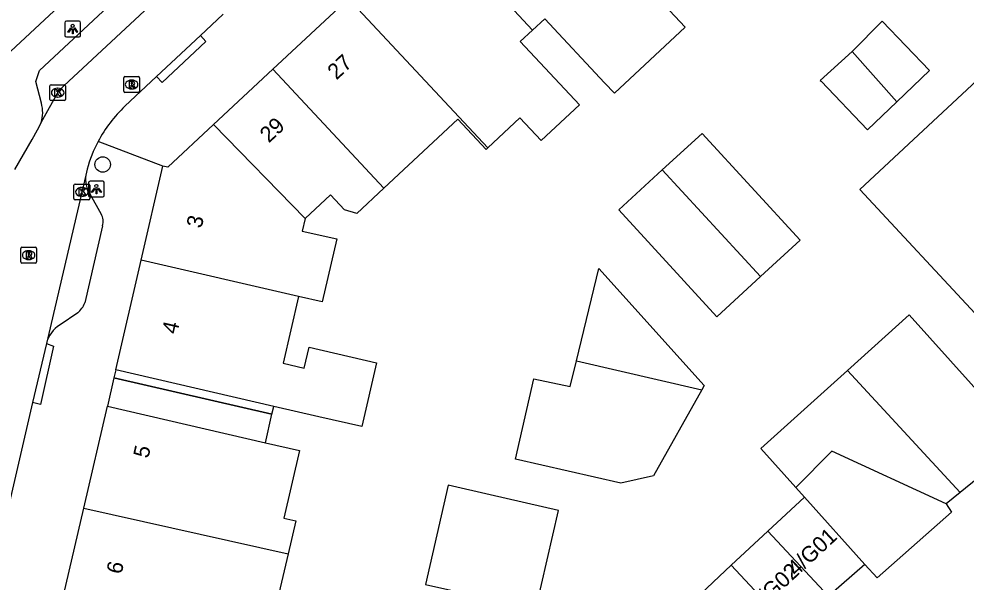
# Model space of a CAD drawing. Extents: x 161801 to 162379, y 382315 to 382832.
# Drawn here: x 161897.6 to 161957.7, y 382637.3 to 382673 of the extents above; entities that cross this region are included whole.
import ezdxf

# ---------------------------------------------------------------- set-up
doc = ezdxf.new("R2010")
doc.units = 0
for name, color, linetype in [('IMGEO_Boom', 7, 'Continuous'), ('IMGEO_Kolk', 7, 'Continuous'), ('IMGEO_Lichtpunt', 7, 'Continuous'), ('IMGEO_Pand', 7, 'Continuous'), ('IMGEO_Pand_nummerreeks', 7, 'Continuous'), ('IMGEO_Pand_overbouw', 7, 'Continuous'), ('IMGEO_Rijbaan_lokaal_open', 7, 'Continuous'), ('IMGEO_Rioolput', 7, 'Continuous'), ('IMGEO_Voetpad_open', 7, 'Continuous')]:
    doc.layers.add(name, color=color, linetype=linetype)

msp = doc.modelspace()

# ---------------------------------------------------------------- linework, layer by layer
at = {"layer": 'IMGEO_Boom'}
msp.add_circle((161902.962, 382663.801), 0.489, dxfattribs=at)
at = {"layer": 'IMGEO_Kolk'}
for p, q in [((161899.61, 382667.935), (161899.61, 382668.787)), ((161899.685, 382668.861), (161900.537, 382668.861)), ((161900.611, 382668.787), (161900.611, 382667.935)), ((161900.098, 382668.641), (161900.123, 382668.641)), ((161900.537, 382667.861), (161899.685, 382667.861)), ((161900.121, 382668.081), (161900.096, 382668.081)), ((161901.139, 382661.639), (161901.139, 382662.491)), ((161901.214, 382662.565), (161902.066, 382662.565)), ((161901.627, 382662.345), (161901.652, 382662.345)), ((161902.14, 382662.491), (161902.14, 382661.639)), ((161902.066, 382661.565), (161901.214, 382661.565)), ((161901.65, 382661.785), (161901.625, 382661.785))]:
    msp.add_line(p, q, dxfattribs=at)
for points in [[(161899.61, 382667.935), (161899.61, 382668.787)], [(161899.685, 382668.861), (161900.537, 382668.861)], [(161900.611, 382668.787), (161900.611, 382667.935)], [(161899.931, 382668.561), (161900.054, 382668.561), (161900.054, 382668.41), (161900.184, 382668.561), (161900.348, 382668.561), (161900.202, 382668.41), (161900.355, 382668.161), (161900.203, 382668.161), (161900.118, 382668.325), (161900.054, 382668.258), (161900.054, 382668.161), (161899.931, 382668.161), (161899.931, 382668.561)], [(161900.537, 382667.861), (161899.685, 382667.861)], [(161901.139, 382661.639), (161901.139, 382662.491)], [(161901.214, 382662.565), (161902.066, 382662.565)], [(161901.46, 382662.265), (161901.583, 382662.265), (161901.583, 382662.114), (161901.713, 382662.265), (161901.877, 382662.265), (161901.731, 382662.114), (161901.884, 382661.865), (161901.732, 382661.865), (161901.647, 382662.029), (161901.583, 382661.962), (161901.583, 382661.865), (161901.46, 382661.865), (161901.46, 382662.265)], [(161902.14, 382662.491), (161902.14, 382661.639)], [(161902.066, 382661.565), (161901.214, 382661.565)]]:
    msp.add_lwpolyline(points, dxfattribs=at)
for centre, start, end in [((161899.687, 382668.785), 91.55205, 178.44795), ((161899.687, 382668.785), 91.55205, 178.44795), ((161900.535, 382668.785), 1.55205, 88.44795), ((161900.535, 382668.785), 1.55205, 88.44795), ((161899.687, 382667.937), 181.55205, 268.44795), ((161899.687, 382667.937), 181.55205, 268.44795), ((161900.535, 382667.937), 271.55205, 358.44795), ((161900.535, 382667.937), 271.55205, 358.44795), ((161901.216, 382662.489), 91.55205, 178.44795), ((161901.216, 382662.489), 91.55205, 178.44795), ((161902.064, 382662.489), 1.55205, 88.44795), ((161902.064, 382662.489), 1.55205, 88.44795), ((161901.216, 382661.641), 181.55205, 268.44795), ((161901.216, 382661.641), 181.55205, 268.44795), ((161902.064, 382661.641), 271.55205, 358.44795), ((161902.064, 382661.641), 271.55205, 358.44795)]:
    msp.add_arc(centre, 0.0765, start, end, dxfattribs=at)
for centre, major_axis, ratio, start_param, end_param in [((161900.097, 382668.361), (-0.387, 0.002), 0.722429, 4.712389, 7.853982), ((161900.122, 382668.361), (-0.39, 0.002), 0.717154, 1.570796, 4.712389), ((161901.626, 382662.065), (-0.387, 0.002), 0.722429, 4.712389, 7.853982), ((161901.651, 382662.065), (-0.39, 0.002), 0.717154, 1.570796, 4.712389)]:
    msp.add_ellipse(centre, major_axis=major_axis, ratio=ratio, start_param=start_param, end_param=end_param, dxfattribs=at)
at = {"layer": 'IMGEO_Lichtpunt'}
for p, q in [((161900.562, 382672.8), (161900.562, 382671.993)), ((161900.562, 382672.8), (161900.562, 382671.993)), ((161901.464, 382672.895), (161900.656, 382672.895)), ((161901.464, 382672.895), (161900.656, 382672.895)), ((161901.558, 382671.993), (161901.558, 382672.8)), ((161901.558, 382671.993), (161901.558, 382672.8)), ((161900.656, 382671.899), (161901.464, 382671.899)), ((161900.656, 382671.899), (161901.464, 382671.899)), ((161902.967, 382662.743), (161902.159, 382662.743)), ((161902.967, 382662.743), (161902.159, 382662.743)), ((161902.065, 382662.648), (161902.065, 382661.841)), ((161902.065, 382662.648), (161902.065, 382661.841)), ((161903.061, 382661.841), (161903.061, 382662.648)), ((161903.061, 382661.841), (161903.061, 382662.648)), ((161902.159, 382661.747), (161902.967, 382661.747)), ((161902.159, 382661.747), (161902.967, 382661.747))]:
    msp.add_line(p, q, dxfattribs=at)
for points in [[(161900.936, 382672.464), (161900.975, 382672.436), (161900.787, 382672.174), (161900.749, 382672.201), (161900.936, 382672.464)], [(161901.038, 382672.416), (161901.085, 382672.416), (161901.085, 382672.094), (161901.038, 382672.094), (161901.038, 382672.416)], [(161901.148, 382672.436), (161901.186, 382672.463), (161901.373, 382672.201), (161901.334, 382672.173), (161901.148, 382672.436)], [(161902.439, 382662.312), (161902.478, 382662.284), (161902.29, 382662.022), (161902.252, 382662.049), (161902.439, 382662.312)], [(161902.541, 382662.264), (161902.588, 382662.264), (161902.588, 382661.942), (161902.541, 382661.942), (161902.541, 382662.264)], [(161902.651, 382662.284), (161902.689, 382662.311), (161902.876, 382662.049), (161902.837, 382662.021), (161902.651, 382662.284)]]:
    msp.add_lwpolyline(points, dxfattribs=at)
for centre in [(161901.061, 382672.598), (161902.564, 382662.446)]:
    msp.add_circle(centre, 0.0994, dxfattribs=at)
for centre, start, end in [((161900.656, 382672.8), 90, 180), ((161900.656, 382672.8), 90, 180), ((161901.464, 382672.8), 0, 90), ((161901.464, 382672.8), 0, 90), ((161900.656, 382671.993), 180, 270), ((161900.656, 382671.993), 180, 270), ((161901.464, 382671.993), 270, 0), ((161901.464, 382671.993), 270, 360), ((161902.159, 382662.648), 90, 180), ((161902.159, 382662.648), 90, 180), ((161902.967, 382662.648), 0, 90), ((161902.967, 382662.648), 0, 90), ((161902.159, 382661.841), 180, 270), ((161902.159, 382661.841), 180, 270), ((161902.967, 382661.841), 270, 0), ((161902.967, 382661.841), 270, 360)]:
    msp.add_arc(centre, 0.0946, start, end, dxfattribs=at)
at = {"layer": 'IMGEO_Pand'}
for points in [[(161930.236, 382672.332), (161923.819, 382679.223)], [(161905.041, 382678.375), (161896.201, 382670.148)], [(161935.76, 382677.538), (161935.478, 382677.275), (161937.606, 382674.998), (161939.923, 382672.519), (161935.425, 382668.32), (161934.802, 382668.987), (161931.006, 382673.051), (161930.236, 382672.332)], [(161913.761, 382669.856), (161918.565, 382674.33)], [(161918.565, 382674.33), (161927.386, 382664.856)], [(161953.342, 382667.786), (161955.416, 382669.771), (161952.418, 382672.904), (161950.514, 382670.968)], [(161930.236, 382672.332), (161929.454, 382671.601), (161933.204, 382667.586), (161930.777, 382665.318), (161929.427, 382666.763), (161927.386, 382664.856)], [(161950.514, 382670.968), (161948.484, 382669.142), (161948.542, 382669.082), (161951.484, 382666.008), (161953.342, 382667.786)], [(161950.514, 382670.968), (161953.342, 382667.786)], [(161971, 382658.776), (161962.003, 382650.399), (161958.595, 382654.059), (161950.996, 382662.22), (161959.963, 382670.569)], [(161909.987, 382666.342), (161913.761, 382669.856)], [(161920.8, 382662.297), (161913.761, 382669.856)], [(161909.987, 382666.342), (161907.086, 382663.64), (161906.786, 382663.708)], [(161915.801, 382660.374), (161909.987, 382666.342)], [(161927.386, 382664.856), (161927.283, 382664.76), (161925.49, 382666.679), (161920.8, 382662.297)], [(161944.698, 382656.702), (161947.208, 382659.005), (161940.99, 382665.78), (161938.46, 382663.459)], [(161905.406, 382657.742), (161906.786, 382663.708)], [(161938.46, 382663.459), (161935.699, 382660.925), (161941.916, 382654.149), (161944.698, 382656.702)], [(161944.698, 382656.702), (161938.46, 382663.459)], [(161920.8, 382662.297), (161919.086, 382660.696), (161918.295, 382660.937), (161917.414, 382661.881), (161915.801, 382660.374)], [(161915.801, 382660.374), (161915.619, 382659.584), (161917.808, 382659.081), (161916.889, 382655.086), (161915.379, 382655.435)], [(161903.793, 382650.769), (161905.406, 382657.742)], [(161915.379, 382655.435), (161905.406, 382657.742)], [(161933.018, 382651.355), (161934.438, 382657.209), (161941.123, 382649.78), (161940.974, 382649.515)], [(161915.379, 382655.435), (161914.405, 382651.2), (161915.754, 382650.89), (161916.059, 382652.214), (161920.327, 382651.232), (161919.395, 382647.18), (161916.672, 382647.806), (161913.816, 382648.463), (161903.793, 382650.769)], [(161950.208, 382650.733), (161954.136, 382654.268), (161959.375, 382648.439), (161959.601, 382644.808), (161957.355, 382642.992)], [(161940.974, 382649.515), (161937.917, 382644.064), (161935.843, 382643.585), (161929.141, 382645.117), (161930.304, 382650.206), (161932.62, 382649.712), (161933.018, 382651.355)], [(161933.018, 382651.355), (161940.974, 382649.515)], [(161946.939, 382643.317), (161944.714, 382645.789), (161950.208, 382650.733)], [(161950.208, 382650.733), (161957.355, 382642.992)], [(161901.764, 382642), (161903.26, 382648.466)], [(161903.26, 382648.466), (161913.285, 382646.159), (161915.449, 382645.661), (161914.463, 382641.375), (161915.209, 382641.203), (161914.727, 382639.11)], [(161956.468, 382642.274), (161949.231, 382645.611), (161946.939, 382643.317)], [(161927.536, 382642.861), (161924.886, 382643.471), (161923.437, 382637.168), (161930.448, 382635.605), (161931.888, 382641.86), (161927.536, 382642.861)], [(161947.485, 382642.71), (161946.939, 382643.317)], [(161957.355, 382642.992), (161956.468, 382642.274)], [(161945.163, 382640.546), (161947.485, 382642.71)], [(161947.485, 382642.71), (161951.321, 382638.442)], [(161900.274, 382635.56), (161901.764, 382642)], [(161901.764, 382642), (161914.727, 382639.11)], [(161956.468, 382642.274), (161956.813, 382641.76), (161952.092, 382637.584), (161951.321, 382638.442)], [(161942.842, 382638.382), (161945.163, 382640.546)], [(161949.005, 382636.425), (161945.163, 382640.546)], [(161914.727, 382639.11), (161913.18, 382632.56), (161910.284, 382633.233)], [(161940.52, 382636.218), (161942.842, 382638.382)], [(161946.681, 382634.263), (161942.842, 382638.382)], [(161951.321, 382638.442), (161949.005, 382636.425)]]:
    msp.add_lwpolyline(points, dxfattribs=at)
at = {"layer": 'IMGEO_Pand_overbouw'}
for points in [[(161903.677, 382650.27), (161913.701, 382647.962), (161913.816, 382648.463), (161903.793, 382650.769)], [(161903.677, 382650.27), (161903.26, 382648.466), (161913.285, 382646.159), (161913.701, 382647.962)]]:
    msp.add_lwpolyline(points, close=True, dxfattribs=at)
at = {"layer": 'IMGEO_Rijbaan_lokaal_open'}
for points in [[(161899.049, 382666.462), (161900.203, 382668.529), (161922.425, 382689.194)], [(161910.6, 382673.34), (161909.875, 382672.652), (161909.162, 382671.985)], [(161909.162, 382671.985), (161906.385, 382669.388)], [(161906.385, 382669.388), (161904.376, 382667.509)], [(161897.396, 382663.481), (161898.479, 382665.384), (161898.831, 382666.002), (161898.991, 382666.31), (161899.049, 382666.462)], [(161901.973, 382663.501), (161901.884, 382663.119)], [(161901.884, 382663.119), (161899.388, 382652.453)], [(161899.388, 382652.453), (161898.518, 382648.702)], [(161898.518, 382648.702), (161892.955, 382624.701)]]:
    msp.add_lwpolyline(points, dxfattribs=at)
for centre, radius, start, end in [((161910.427, 382661.158), 8.773, 133.61353, 152.11861), ((161910.391, 382661.17), 8.735, 152.0788, 164.5207)]:
    msp.add_arc(centre, radius, start, end, dxfattribs=at)
at = {"layer": 'IMGEO_Rioolput'}
for p, q in [((161904.372, 382669.378), (161905.224, 382669.378)), ((161904.297, 382668.452), (161904.297, 382669.304)), ((161904.785, 382669.158), (161904.81, 382669.158)), ((161905.298, 382669.304), (161905.298, 382668.452)), ((161905.224, 382668.378), (161904.372, 382668.378)), ((161904.808, 382668.598), (161904.783, 382668.598)), ((161897.84, 382658.553), (161898.692, 382658.553)), ((161897.765, 382657.627), (161897.765, 382658.479)), ((161898.253, 382658.333), (161898.278, 382658.333)), ((161898.766, 382658.479), (161898.766, 382657.627)), ((161898.692, 382657.553), (161897.84, 382657.553)), ((161898.276, 382657.773), (161898.251, 382657.773))]:
    msp.add_line(p, q, dxfattribs=at)
for points in [[(161904.372, 382669.378), (161905.224, 382669.378)], [(161904.297, 382668.452), (161904.297, 382669.304)], [(161904.886, 382669.076), (161904.634, 382669.078), (161904.634, 382668.678)], [(161904.634, 382668.678), (161904.758, 382668.678), (161904.758, 382668.84), (161904.769, 382668.84)], [(161904.812, 382668.997), (161904.758, 382668.997), (161904.758, 382668.916)], [(161904.758, 382668.916), (161904.81, 382668.916)], [(161904.816, 382668.811), (161904.887, 382668.678), (161905.027, 382668.678), (161904.962, 382668.804)], [(161905.298, 382669.304), (161905.298, 382668.452)], [(161905.224, 382668.378), (161904.372, 382668.378)], [(161897.84, 382658.553), (161898.692, 382658.553)], [(161897.765, 382657.627), (161897.765, 382658.479)], [(161898.354, 382658.251), (161898.102, 382658.253), (161898.102, 382657.853)], [(161898.102, 382657.853), (161898.226, 382657.853), (161898.226, 382658.015), (161898.237, 382658.015)], [(161898.28, 382658.172), (161898.226, 382658.172), (161898.226, 382658.091)], [(161898.226, 382658.091), (161898.278, 382658.091)], [(161898.284, 382657.986), (161898.355, 382657.853), (161898.495, 382657.853), (161898.43, 382657.979)], [(161898.766, 382658.479), (161898.766, 382657.627)], [(161898.692, 382657.553), (161897.84, 382657.553)]]:
    msp.add_lwpolyline(points, dxfattribs=at)
for centre, radius, start, end in [((161904.374, 382669.302), 0.0765, 91.55205, 178.44795), ((161904.374, 382669.302), 0.0765, 91.55205, 178.44795), ((161905.222, 382669.302), 0.0765, 1.55205, 88.44795), ((161905.222, 382669.302), 0.0765, 1.55205, 88.44795), ((161904.768, 382668.787), 0.0533, 26.02933, 88.69889), ((161904.794, 382669.105), 0.19, 274.7715, 282.96867), ((161904.818, 382668.901), 0.0964, 77.00612, 93.18647), ((161904.832, 382668.958), 0.0378, 276.66336, 79.67722), ((161904.885, 382668.966), 0.109, 350.36119, 89.41601), ((161904.883, 382668.966), 0.112, 277.58423, 350.98172), ((161904.867, 382668.751), 0.108, 29.51342, 73.79051), ((161904.374, 382668.454), 0.0765, 181.55205, 268.44795), ((161904.374, 382668.454), 0.0765, 181.55205, 268.44795), ((161905.222, 382668.454), 0.0765, 271.55205, 358.44795), ((161905.222, 382668.454), 0.0765, 271.55205, 358.44795), ((161897.842, 382658.477), 0.0765, 91.55205, 178.44795), ((161897.842, 382658.477), 0.0765, 91.55205, 178.44795), ((161898.69, 382658.477), 0.0765, 1.55205, 88.44795), ((161898.69, 382658.477), 0.0765, 1.55205, 88.44795), ((161898.236, 382657.962), 0.0533, 26.02933, 88.69889), ((161898.262, 382658.28), 0.19, 274.7715, 282.96867), ((161898.286, 382658.076), 0.0964, 77.00612, 93.18647), ((161898.3, 382658.133), 0.0378, 276.66336, 79.67722), ((161898.353, 382658.141), 0.109, 350.36119, 89.41601), ((161898.351, 382658.141), 0.112, 277.58423, 350.98172), ((161898.335, 382657.926), 0.108, 29.51342, 73.79051), ((161897.842, 382657.629), 0.0765, 181.55205, 268.44795), ((161897.842, 382657.629), 0.0765, 181.55205, 268.44795), ((161898.69, 382657.629), 0.0765, 271.55205, 358.44795), ((161898.69, 382657.629), 0.0765, 271.55205, 358.44795)]:
    msp.add_arc(centre, radius, start, end, dxfattribs=at)
for centre, major_axis, ratio, start_param, end_param in [((161904.784, 382668.878), (-0.387, 0.002), 0.722429, 4.712389, 7.853982), ((161904.809, 382668.878), (-0.39, 0.002), 0.717154, 1.570796, 4.712389), ((161898.252, 382658.053), (-0.387, 0.002), 0.722429, 4.712389, 7.853982), ((161898.277, 382658.053), (-0.39, 0.002), 0.717154, 1.570796, 4.712389)]:
    msp.add_ellipse(centre, major_axis=major_axis, ratio=ratio, start_param=start_param, end_param=end_param, dxfattribs=at)
at = {"layer": 'IMGEO_Voetpad_open'}
for points in [[(161899.069, 382667.689), (161898.728, 382669.061), (161898.946, 382669.761), (161919.116, 382688.561)], [(161909.162, 382671.985), (161909.511, 382671.614), (161906.741, 382669.009), (161906.385, 382669.388)], [(161906.786, 382663.708), (161902.673, 382665.26)], [(161902.151, 382661.935), (161902.864, 382660.664)], [(161902.959, 382659.919), (161901.824, 382655.028)], [(161901.374, 382654.401), (161900.256, 382653.637)], [(161899.388, 382652.453), (161899.851, 382652.271), (161899.011, 382648.59), (161898.518, 382648.702)], [(161903.793, 382650.769), (161903.677, 382650.27), (161903.26, 382648.466)]]:
    msp.add_lwpolyline(points, dxfattribs=at)
for centre, radius, start, end in [((161897.126, 382667.107), 2.029, 341.46172, 16.67062), ((161903.676, 382662.901), 1.805, 173.0668, 212.34923), ((161902.018, 382660.178), 0.976, 344.64709, 29.88682), ((161900.548, 382655.469), 1.35, 307.7251, 340.94064), ((161901.29, 382651.969), 1.963, 121.79554, 165.71357)]:
    msp.add_arc(centre, radius, start, end, dxfattribs=at)

# ---------------------------------------------------------------- texts
at = {"layer": 'IMGEO_Pand_nummerreeks'}
for s, rotation, p in [('27', 42.96157, (161917.793, 382669.13)), ('29', 42.96157, (161913.504, 382665.136)), ('3', 76.97115, (161909.229, 382659.718)), ('4', 76.97115, (161907.675, 382652.999)), ('5', 76.97115, (161905.854, 382645.128)), ('4/G01', 42.90475, (161946.962, 382637.629)), ('6', 76.97392, (161904.152, 382637.772)), ('4/G02', 42.90475, (161944.566, 382635.402))]:
    msp.add_text(s, height=1, rotation=rotation, dxfattribs=at).set_placement(p)

doc.saveas('drawing.dxf')
